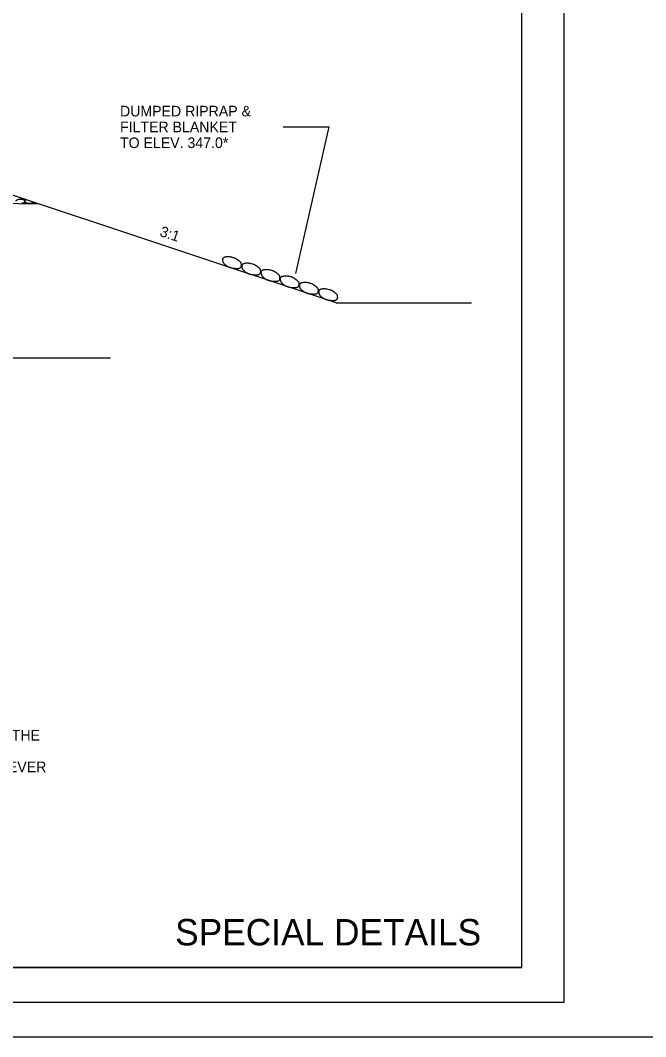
# Model space of a CAD drawing. Extents: x 3575 to 11445, y 9479 to 13278.
# Drawn here: x 7181 to 7536, y 10000 to 10578 of the extents above; entities that cross this region are included whole.
import ezdxf

# ---------------------------------------------------------------- set-up
doc = ezdxf.new("R2010")
doc.units = 0
for name, color, linetype in [('_Drafting 1', 7, 'Continuous'), ('Agg Base Course Text', 7, 'Continuous'), ('Aggregate Base Course', 7, 'Continuous'), ('Default', 7, 'Continuous'), ('R_Dimension', 7, 'Continuous'), ('R_NoPlot', 7, 'Continuous'), ('STAMP_PE_CRAFTON-SIGNATURE', 7, 'Continuous'), ('STAMP_PRELIMINARY', 7, 'Continuous')]:
    doc.layers.add(name, color=color, linetype=linetype)

msp = doc.modelspace()

# ---------------------------------------------------------------- linework, layer by layer
at = {"layer": '_Drafting 1'}
msp.add_lwpolyline([(5884.86, 11066.7), (5884.86, 10039.4), (7465.76, 10039.4), (7465.76, 11002.7), (7250.26, 11002.7), (7250.26, 11001.26), (7234.07, 11001.26), (7234.07, 11017.3), (7054.46, 11017.3), (7054.46, 11066.7)], close=True, dxfattribs=at)
at = {"layer": 'Agg Base Course Text'}
msp.add_line((7330.03, 10517.26), (7356.09, 10517.26), dxfattribs=at)
msp.add_lwpolyline([(7356.09, 10517.26), (7337.13, 10433.97)], dxfattribs=at)
at = {"layer": 'Aggregate Base Course'}
for points, degree in [([(7183.87, 10475.93), (7183.84, 10475.93), (7183.81, 10475.92), (7183.64, 10475.91), (7183.49, 10475.91), (7183.13, 10475.94), (7182.91, 10475.96), (7182.44, 10476.01), (7182.2, 10476.05), (7181.77, 10476.15), (7181.6, 10476.25), (7181.23, 10476.49), (7181.07, 10476.61), (7180.9, 10476.86), (7180.89, 10476.89), (7180.87, 10476.93)], 3), ([(7178.29, 10474.98), (7178.29, 10474.99), (7178.29, 10475), (7178.29, 10475), (7178.29, 10475.17), (7178.34, 10475.33), (7178.45, 10475.48), (7178.56, 10475.63), (7178.69, 10475.72), (7178.85, 10475.8), (7178.98, 10475.87), (7179.11, 10475.94), (7179.25, 10475.98), (7179.44, 10476.05), (7179.64, 10476.11), (7179.85, 10476.16), (7179.97, 10476.19), (7180.1, 10476.22), (7180.23, 10476.24), (7180.41, 10476.27), (7180.6, 10476.28), (7180.79, 10476.26)], 3), ([(7180.79, 10476.26), (7180.81, 10476.26), (7180.83, 10476.26), (7180.85, 10476.26)], 2), ([(7180.85, 10476.26), (7181.14, 10476.27), (7181.43, 10476.22), (7181.73, 10476.16), (7182.08, 10476.09), (7182.41, 10475.98), (7182.75, 10475.8), (7182.97, 10475.68), (7183.14, 10475.53), (7183.27, 10475.3), (7183.32, 10475.2), (7183.34, 10475.11), (7183.35, 10475), (7183.35, 10475), (7183.35, 10474.99), (7183.35, 10474.98)], 3), ([(7183.23, 10474.98), (7183.23, 10474.96), (7183.23, 10474.94), (7183.22, 10474.72), (7183.09, 10474.54), (7182.86, 10474.28), (7182.76, 10474.21), (7182.44, 10474.03), (7182.25, 10473.93), (7181.82, 10473.8), (7181.61, 10473.74), (7181.4, 10473.7)], 3), ([(7181.56, 10473.7), (7181.64, 10473.74), (7181.72, 10473.77), (7182, 10473.87), (7182.2, 10473.93), (7182.53, 10474.01), (7182.66, 10474.04), (7182.97, 10474.09), (7183.16, 10474.1), (7183.35, 10474.08)], 3), ([(7185.91, 10473.68), (7185.88, 10473.68), (7185.85, 10473.68), (7185.83, 10473.68), (7185.61, 10473.68), (7185.39, 10473.7), (7185.17, 10473.74), (7184.93, 10473.78), (7184.71, 10473.86), (7184.48, 10473.92), (7184.29, 10473.98), (7184.1, 10474.04), (7183.91, 10474.12), (7183.69, 10474.21), (7183.52, 10474.37), (7183.41, 10474.58), (7183.35, 10474.69), (7183.33, 10474.81), (7183.33, 10474.92), (7183.33, 10474.94), (7183.33, 10474.96), (7183.33, 10474.98)], 3), ([(7183.35, 10474.08), (7183.64, 10474.09), (7183.93, 10474.04), (7184.58, 10473.91), (7184.91, 10473.8), (7185.24, 10473.63)], 3), ([(7183.41, 10474.98), (7183.41, 10474.99), (7183.41, 10475), (7183.41, 10475.17), (7183.46, 10475.33), (7183.68, 10475.63), (7183.81, 10475.72), (7184, 10475.82), (7184.04, 10475.84), (7184.08, 10475.86)], 3), ([(7188.16, 10474.5), (7188.13, 10474.46), (7188.1, 10474.42), (7187.98, 10474.28), (7187.88, 10474.21), (7187.56, 10474.03), (7187.37, 10473.93), (7186.86, 10473.77), (7186.58, 10473.69), (7186.16, 10473.68), (7186.03, 10473.68), (7185.91, 10473.68)], 3), ([(7186.49, 10473.6), (7186.5, 10473.61), (7186.51, 10473.62), (7186.66, 10473.69), (7186.79, 10473.76), (7187.12, 10473.87), (7187.32, 10473.93), (7187.65, 10474.01), (7187.78, 10474.04), (7188.09, 10474.09), (7188.28, 10474.1), (7188.47, 10474.08)], 3), ([(7188.47, 10474.08), (7188.76, 10474.09), (7189.05, 10474.04), (7189.7, 10473.91), (7190.03, 10473.8), (7190.42, 10473.59), (7190.48, 10473.56), (7190.52, 10473.52)], 3), ([(7190.54, 10473.71), (7190.45, 10473.71), (7190.37, 10473.73), (7190.05, 10473.78), (7189.83, 10473.86), (7189.41, 10473.98), (7189.22, 10474.04), (7188.92, 10474.17), (7188.82, 10474.23), (7188.74, 10474.3)], 3), ([(7301.72, 10442.89), (7301.1, 10443.11), (7300.44, 10443.23), (7299.78, 10443.31), (7298.96, 10443.41), (7298.18, 10443.41), (7297.34, 10443.26), (7296.78, 10443.17), (7296.3, 10442.96), (7295.88, 10442.57), (7295.69, 10442.4), (7295.58, 10442.2), (7295.49, 10441.98), (7295.49, 10441.97), (7295.48, 10441.96), (7295.48, 10441.94)], 3), ([(7301.85, 10442.85), (7301.81, 10442.86), (7301.77, 10442.88), (7301.72, 10442.89)], 2), ([(7306.28, 10438.34), (7306.28, 10438.36), (7306.29, 10438.37), (7306.29, 10438.38), (7306.4, 10438.75), (7306.42, 10439.13), (7306.29, 10439.52), (7306.17, 10439.92), (7305.94, 10440.21), (7305.67, 10440.49), (7305.43, 10440.73), (7305.2, 10440.96), (7304.94, 10441.16), (7304.56, 10441.44), (7304.18, 10441.71), (7303.79, 10441.97), (7303.54, 10442.13), (7303.29, 10442.28), (7303.03, 10442.41), (7302.66, 10442.6), (7302.26, 10442.75), (7301.85, 10442.85)], 3), ([(7295.73, 10441.86), (7295.72, 10441.81), (7295.7, 10441.77), (7295.69, 10441.73), (7295.56, 10441.29), (7295.71, 10440.82), (7295.9, 10440.38), (7296.03, 10440.09), (7296.18, 10439.87), (7296.37, 10439.65), (7296.72, 10439.26), (7297.08, 10438.92), (7297.5, 10438.61), (7298.04, 10438.22), (7298.59, 10437.85), (7299.21, 10437.61), (7299.47, 10437.51), (7299.74, 10437.42), (7300.02, 10437.34)], 3), ([(7300.02, 10437.34), (7300.07, 10437.33), (7300.13, 10437.31), (7300.19, 10437.29), (7300.66, 10437.13), (7301.14, 10437.02), (7301.64, 10436.95), (7302.17, 10436.87), (7302.69, 10436.86), (7303.23, 10436.84), (7303.69, 10436.82), (7304.14, 10436.82), (7304.6, 10436.86), (7305.12, 10436.9), (7305.6, 10437.11), (7305.99, 10437.49), (7306.2, 10437.68), (7306.32, 10437.91), (7306.41, 10438.16), (7306.42, 10438.2), (7306.43, 10438.24), (7306.45, 10438.28)], 3), ([(7312.65, 10439.25), (7312.03, 10439.47), (7311.37, 10439.58), (7310.7, 10439.66), (7309.89, 10439.76), (7309.11, 10439.76), (7308.27, 10439.62), (7307.71, 10439.53), (7307.23, 10439.32), (7306.8, 10438.92), (7306.62, 10438.75), (7306.51, 10438.56), (7306.42, 10438.34), (7306.41, 10438.33), (7306.41, 10438.31), (7306.41, 10438.3)], 3), ([(7306.66, 10438.21), (7306.65, 10438.17), (7306.63, 10438.13), (7306.62, 10438.08), (7306.49, 10437.65), (7306.64, 10437.18), (7306.83, 10436.73), (7306.95, 10436.45), (7307.11, 10436.23), (7307.3, 10436.01), (7307.65, 10435.62), (7308.01, 10435.27), (7308.43, 10434.97), (7308.97, 10434.57), (7309.52, 10434.2), (7310.13, 10433.97), (7310.4, 10433.87), (7310.67, 10433.78), (7310.95, 10433.7)], 3), ([(7312.78, 10439.21), (7312.74, 10439.22), (7312.7, 10439.24), (7312.65, 10439.25)], 2), ([(7317.21, 10434.7), (7317.21, 10434.71), (7317.22, 10434.73), (7317.22, 10434.74), (7317.33, 10435.1), (7317.35, 10435.48), (7317.22, 10435.88), (7317.09, 10436.28), (7316.87, 10436.57), (7316.6, 10436.85), (7316.36, 10437.09), (7316.13, 10437.32), (7315.87, 10437.52), (7315.49, 10437.8), (7315.11, 10438.07), (7314.72, 10438.33), (7314.47, 10438.49), (7314.22, 10438.63), (7313.96, 10438.77), (7313.59, 10438.96), (7313.19, 10439.11), (7312.78, 10439.21)], 3), ([(7310.95, 10433.7), (7311, 10433.68), (7311.06, 10433.66), (7311.12, 10433.64), (7311.59, 10433.49), (7312.07, 10433.38), (7312.57, 10433.3), (7313.1, 10433.23), (7313.62, 10433.22), (7314.15, 10433.2), (7314.61, 10433.18), (7315.06, 10433.18), (7315.53, 10433.22), (7316.04, 10433.26), (7316.53, 10433.46), (7316.92, 10433.84), (7317.12, 10434.04), (7317.25, 10434.26), (7317.34, 10434.51), (7317.35, 10434.56), (7317.36, 10434.6), (7317.38, 10434.64)], 3), ([(7323.58, 10435.61), (7322.96, 10435.83), (7322.3, 10435.94), (7321.63, 10436.02), (7320.82, 10436.12), (7320.03, 10436.12), (7319.2, 10435.98), (7318.64, 10435.88), (7318.15, 10435.68), (7317.73, 10435.28), (7317.55, 10435.11), (7317.44, 10434.91), (7317.35, 10434.7), (7317.34, 10434.68), (7317.34, 10434.67), (7317.34, 10434.66)], 3), ([(7317.59, 10434.57), (7317.58, 10434.53), (7317.56, 10434.48), (7317.55, 10434.44), (7317.42, 10434), (7317.57, 10433.54), (7317.76, 10433.09), (7317.88, 10432.81), (7318.03, 10432.58), (7318.23, 10432.36), (7318.58, 10431.98), (7318.94, 10431.63), (7319.36, 10431.33), (7319.9, 10430.93), (7320.45, 10430.56), (7321.06, 10430.33), (7321.33, 10430.23), (7321.6, 10430.14), (7321.87, 10430.06)], 3), ([(7321.87, 10430.06), (7321.93, 10430.04), (7321.99, 10430.02), (7322.05, 10430), (7322.52, 10429.84), (7323, 10429.73), (7323.5, 10429.66), (7324.03, 10429.58), (7324.55, 10429.58), (7325.08, 10429.55), (7325.54, 10429.54), (7325.99, 10429.54), (7326.46, 10429.57), (7326.97, 10429.62), (7327.46, 10429.82), (7327.85, 10430.2), (7328.05, 10430.4), (7328.18, 10430.62), (7328.26, 10430.87), (7328.28, 10430.91), (7328.29, 10430.96), (7328.31, 10431)], 3), ([(7323.71, 10435.57), (7323.67, 10435.58), (7323.63, 10435.6), (7323.58, 10435.61)], 2), ([(7328.14, 10431.05), (7328.14, 10431.07), (7328.15, 10431.08), (7328.15, 10431.1), (7328.26, 10431.46), (7328.28, 10431.84), (7328.15, 10432.24), (7328.02, 10432.64), (7327.8, 10432.92), (7327.52, 10433.2), (7327.29, 10433.44), (7327.06, 10433.67), (7326.8, 10433.87), (7326.42, 10434.16), (7326.04, 10434.43), (7325.65, 10434.68), (7325.4, 10434.84), (7325.15, 10434.99), (7324.89, 10435.12), (7324.52, 10435.32), (7324.12, 10435.47), (7323.71, 10435.57)], 3), ([(7334.51, 10431.97), (7333.89, 10432.18), (7333.23, 10432.3), (7332.56, 10432.38), (7331.75, 10432.48), (7330.96, 10432.48), (7330.13, 10432.34), (7329.57, 10432.24), (7329.08, 10432.04), (7328.66, 10431.64), (7328.48, 10431.47), (7328.37, 10431.27), (7328.28, 10431.05), (7328.27, 10431.04), (7328.27, 10431.03), (7328.26, 10431.01)], 3), ([(7328.52, 10430.93), (7328.5, 10430.88), (7328.49, 10430.84), (7328.48, 10430.8), (7328.35, 10430.36), (7328.5, 10429.89), (7328.69, 10429.45), (7328.81, 10429.16), (7328.96, 10428.94), (7329.16, 10428.72), (7329.51, 10428.33), (7329.86, 10427.99), (7330.28, 10427.68), (7330.83, 10427.29), (7331.38, 10426.92), (7331.99, 10426.69), (7332.26, 10426.59), (7332.53, 10426.49), (7332.8, 10426.42)], 3), ([(7334.64, 10431.92), (7334.6, 10431.93), (7334.55, 10431.95), (7334.51, 10431.97)], 2), ([(7339.06, 10427.41), (7339.07, 10427.43), (7339.07, 10427.44), (7339.08, 10427.45), (7339.19, 10427.82), (7339.2, 10428.2), (7339.08, 10428.59), (7338.95, 10428.99), (7338.72, 10429.28), (7338.45, 10429.56), (7338.22, 10429.8), (7337.99, 10430.03), (7337.73, 10430.23), (7337.35, 10430.51), (7336.97, 10430.78), (7336.57, 10431.04), (7336.33, 10431.2), (7336.08, 10431.35), (7335.82, 10431.48), (7335.45, 10431.68), (7335.05, 10431.83), (7334.64, 10431.92)], 3), ([(7332.8, 10426.42), (7332.86, 10426.4), (7332.92, 10426.38), (7332.97, 10426.36), (7333.45, 10426.2), (7333.93, 10426.09), (7334.43, 10426.02), (7334.95, 10425.94), (7335.48, 10425.93), (7336.01, 10425.91), (7336.47, 10425.89), (7336.92, 10425.89), (7337.39, 10425.93), (7337.9, 10425.98), (7338.39, 10426.18), (7338.78, 10426.56), (7338.98, 10426.75), (7339.11, 10426.98), (7339.19, 10427.23), (7339.21, 10427.27), (7339.22, 10427.31), (7339.24, 10427.35)], 3), ([(7345.44, 10428.32), (7344.82, 10428.54), (7344.16, 10428.65), (7343.49, 10428.74), (7342.67, 10428.83), (7341.89, 10428.84), (7341.06, 10428.69), (7340.5, 10428.6), (7340.01, 10428.39), (7339.59, 10428), (7339.41, 10427.82), (7339.3, 10427.63), (7339.21, 10427.41), (7339.2, 10427.4), (7339.19, 10427.38), (7339.19, 10427.37)], 3), ([(7339.45, 10427.28), (7339.43, 10427.24), (7339.42, 10427.2), (7339.41, 10427.16), (7339.28, 10426.72), (7339.43, 10426.25), (7339.62, 10425.8), (7339.74, 10425.52), (7339.89, 10425.3), (7340.09, 10425.08), (7340.44, 10424.69), (7340.79, 10424.34), (7341.21, 10424.04), (7341.76, 10423.65), (7342.3, 10423.28), (7342.92, 10423.04), (7343.19, 10422.94), (7343.46, 10422.85), (7343.73, 10422.77)], 3), ([(7345.57, 10428.28), (7345.52, 10428.29), (7345.48, 10428.31), (7345.44, 10428.32)], 2), ([(7349.99, 10423.77), (7350, 10423.78), (7350, 10423.8), (7350.01, 10423.81), (7350.12, 10424.17), (7350.13, 10424.55), (7350.01, 10424.95), (7349.88, 10425.35), (7349.65, 10425.64), (7349.38, 10425.92), (7349.15, 10426.16), (7348.92, 10426.39), (7348.66, 10426.59), (7348.28, 10426.87), (7347.9, 10427.14), (7347.5, 10427.4), (7347.26, 10427.56), (7347.01, 10427.7), (7346.75, 10427.84), (7346.37, 10428.03), (7345.98, 10428.18), (7345.57, 10428.28)], 3), ([(7356.37, 10424.68), (7355.75, 10424.9), (7355.09, 10425.01), (7354.42, 10425.09), (7353.6, 10425.19), (7352.82, 10425.19), (7351.99, 10425.05), (7351.43, 10424.95), (7350.94, 10424.75), (7350.52, 10424.35), (7350.34, 10424.18), (7350.23, 10423.98), (7350.14, 10423.77), (7350.13, 10423.76), (7350.12, 10423.74), (7350.12, 10423.73)], 3), ([(7343.73, 10422.77), (7343.79, 10422.75), (7343.85, 10422.73), (7343.9, 10422.72), (7344.37, 10422.56), (7344.86, 10422.45), (7345.35, 10422.37), (7345.88, 10422.3), (7346.41, 10422.29), (7346.94, 10422.27), (7347.4, 10422.25), (7347.85, 10422.25), (7348.31, 10422.29), (7348.83, 10422.33), (7349.32, 10422.53), (7349.71, 10422.92), (7349.91, 10423.11), (7350.04, 10423.34), (7350.12, 10423.58), (7350.14, 10423.63), (7350.15, 10423.67), (7350.16, 10423.71)], 3), ([(7350.38, 10423.64), (7350.36, 10423.6), (7350.35, 10423.56), (7350.34, 10423.51), (7350.21, 10423.07), (7350.36, 10422.61), (7350.55, 10422.16), (7350.67, 10421.88), (7350.82, 10421.65), (7351.02, 10421.44), (7351.37, 10421.05), (7351.72, 10420.7), (7352.14, 10420.4), (7352.68, 10420), (7353.23, 10419.63), (7353.85, 10419.4), (7354.12, 10419.3), (7354.39, 10419.21), (7354.66, 10419.13)], 3), ([(7354.66, 10419.13), (7354.72, 10419.11), (7354.78, 10419.09), (7354.83, 10419.07), (7355.3, 10418.92), (7355.79, 10418.8), (7356.28, 10418.73), (7356.81, 10418.65), (7357.34, 10418.65), (7357.87, 10418.63), (7358.33, 10418.61), (7358.78, 10418.61), (7359.24, 10418.65), (7359.76, 10418.69), (7360.25, 10418.89), (7360.64, 10419.27), (7360.84, 10419.47), (7360.97, 10419.69), (7361.05, 10419.94), (7361.06, 10419.98), (7361.08, 10420.03), (7361.09, 10420.07)], 3), ([(7356.5, 10424.64), (7356.45, 10424.65), (7356.41, 10424.67), (7356.37, 10424.68)], 2), ([(7360.92, 10420.13), (7360.93, 10420.14), (7360.93, 10420.15), (7360.94, 10420.17), (7361.05, 10420.53), (7361.06, 10420.91), (7360.94, 10421.31), (7360.81, 10421.71), (7360.58, 10421.99), (7360.31, 10422.27), (7360.08, 10422.51), (7359.85, 10422.74), (7359.58, 10422.94), (7359.21, 10423.23), (7358.83, 10423.5), (7358.43, 10423.75), (7358.19, 10423.91), (7357.94, 10424.06), (7357.68, 10424.2), (7357.3, 10424.39), (7356.9, 10424.54), (7356.5, 10424.64)], 3)]:
    msp.add_open_spline(points, degree=degree, dxfattribs=at)
at = {"layer": 'Default'}
for p, q in [((7360.17, 10417.16), (7144.73, 10488.97)), ((6994.57, 10477.44), (7191.12, 10473.51)), ((7360.17, 10417.16), (7437.13, 10417.16))]:
    msp.add_line(p, q, dxfattribs=at)
at = {"layer": 'R_Dimension'}
msp.add_line((6742.53, 10386.06), (7232, 10386.06), dxfattribs=at)
at = {"layer": 'R_NoPlot'}
msp.add_lwpolyline([(5822.82, 11086.17), (7489.52, 11086.17), (7489.52, 10019.49), (5822.82, 10019.49)], close=True, dxfattribs=at)
at = {"layer": 'STAMP_PRELIMINARY'}
for p, q in [((7465.76, 10039.4), (7465.76, 11066.7)), ((7465.76, 10039.4), (5884.86, 10039.4)), ((5728.76, 10000), (7488.76, 10000)), ((7488.58, 10000), (9248.58, 10000))]:
    msp.add_line(p, q, dxfattribs=at)

# ---------------------------------------------------------------- texts
at = {"layer": 'Agg Base Course Text'}
for s, p in [('DUMPED RIPRAP &', (7237.35, 10523.26)), ('FILTER BLANKET', (7237.35, 10514.26)), ('TO ELEV. 347.0*', (7237.35, 10505.26))]:
    msp.add_text(s, height=6, dxfattribs=at).set_placement(p)
at = {"layer": 'R_Dimension'}
msp.add_text('3:1', height=6, rotation=341.565, dxfattribs=at).set_placement((7259.49, 10455.38))
at = {"layer": 'STAMP_PE_CRAFTON-SIGNATURE'}
for s, p in [('* RIPRAP ELEVATION SHALL MATCH THE ', (7032.74, 10168.39)), ('  STREAM BANK ELEVATION, WHICHEVER ', (7032.74, 10150.39))]:
    msp.add_text(s, height=6, dxfattribs=at).set_placement(p)
at = {"layer": 'STAMP_PRELIMINARY'}
msp.add_text('SPECIAL DETAILS', height=15, dxfattribs=at).set_placement((7268.67, 10051.9))

doc.saveas('drawing.dxf')
